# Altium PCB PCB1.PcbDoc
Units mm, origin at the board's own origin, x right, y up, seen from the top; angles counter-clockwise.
Board outline 150 x 100 mm, 8 copper layers (Top Layer, GND02, SIG03, SIG04, SIG05, SIG06, PWR07, Bottom Layer), stack 1.535 mm thick; 98 components, 234 nets, 1115 pads, 0 vias.
Unrouted connection lines stored in the file: 524.
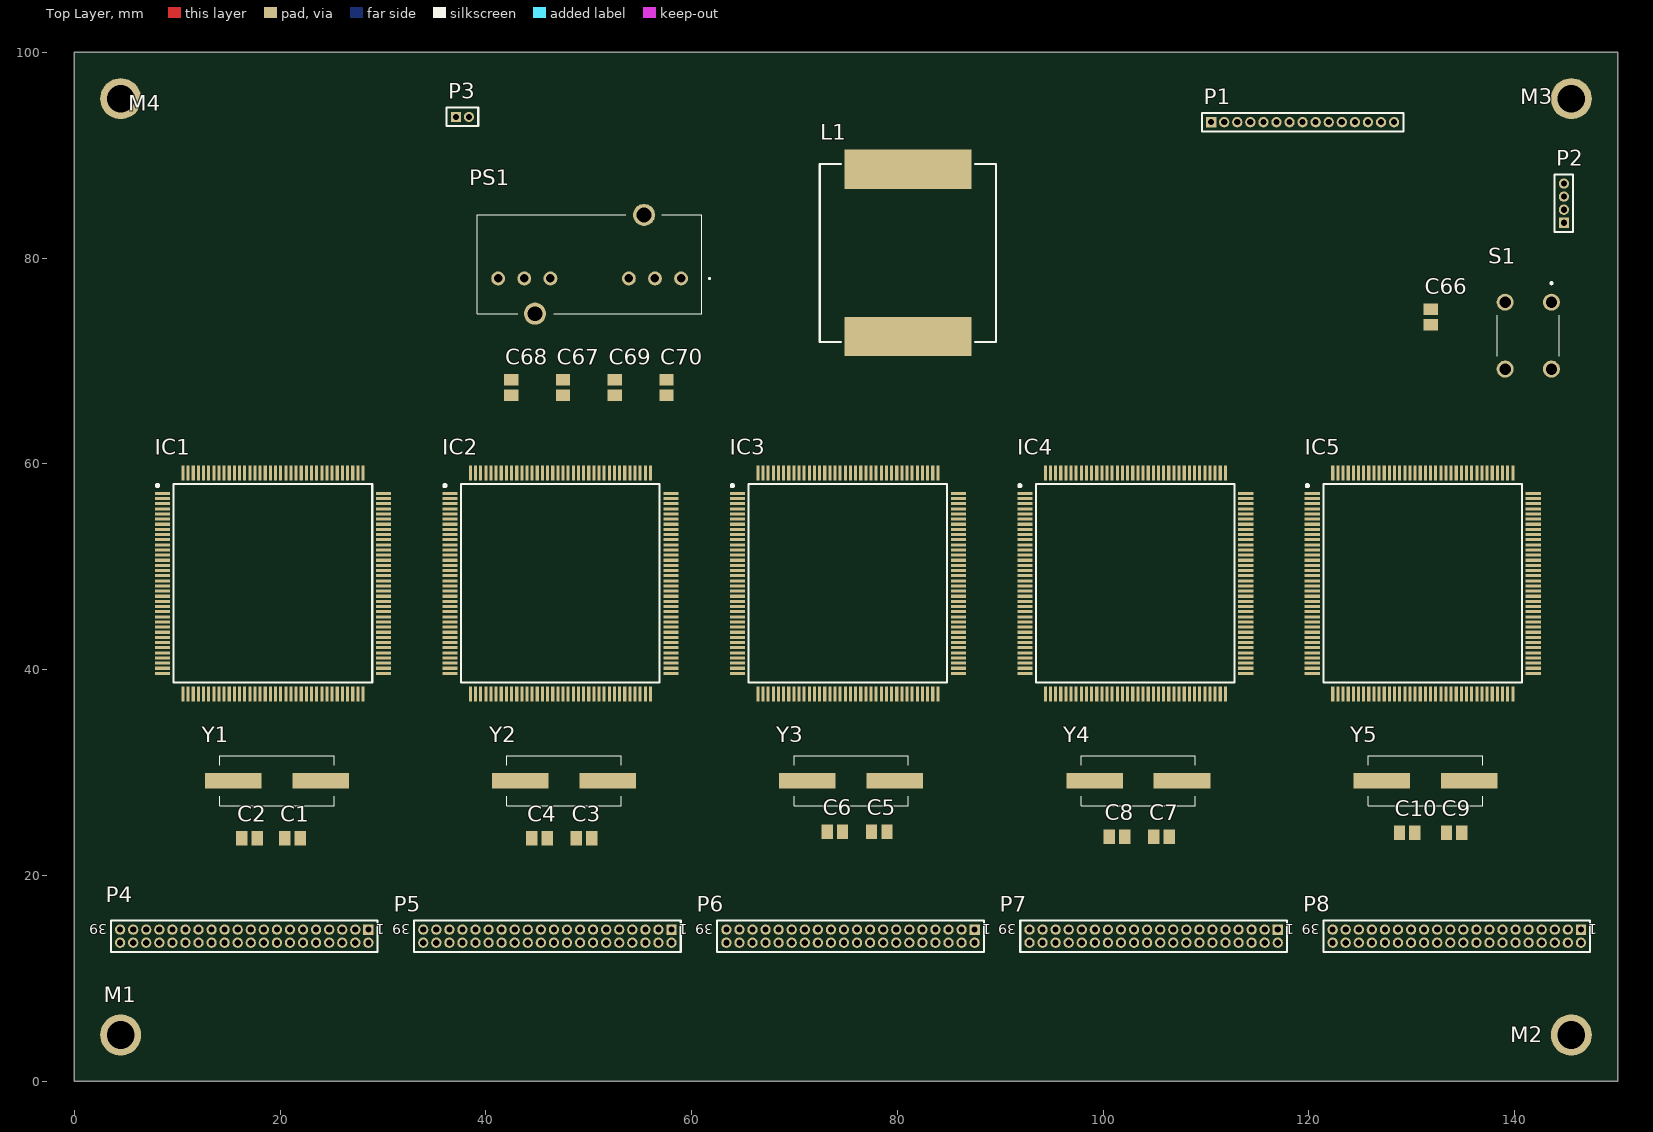
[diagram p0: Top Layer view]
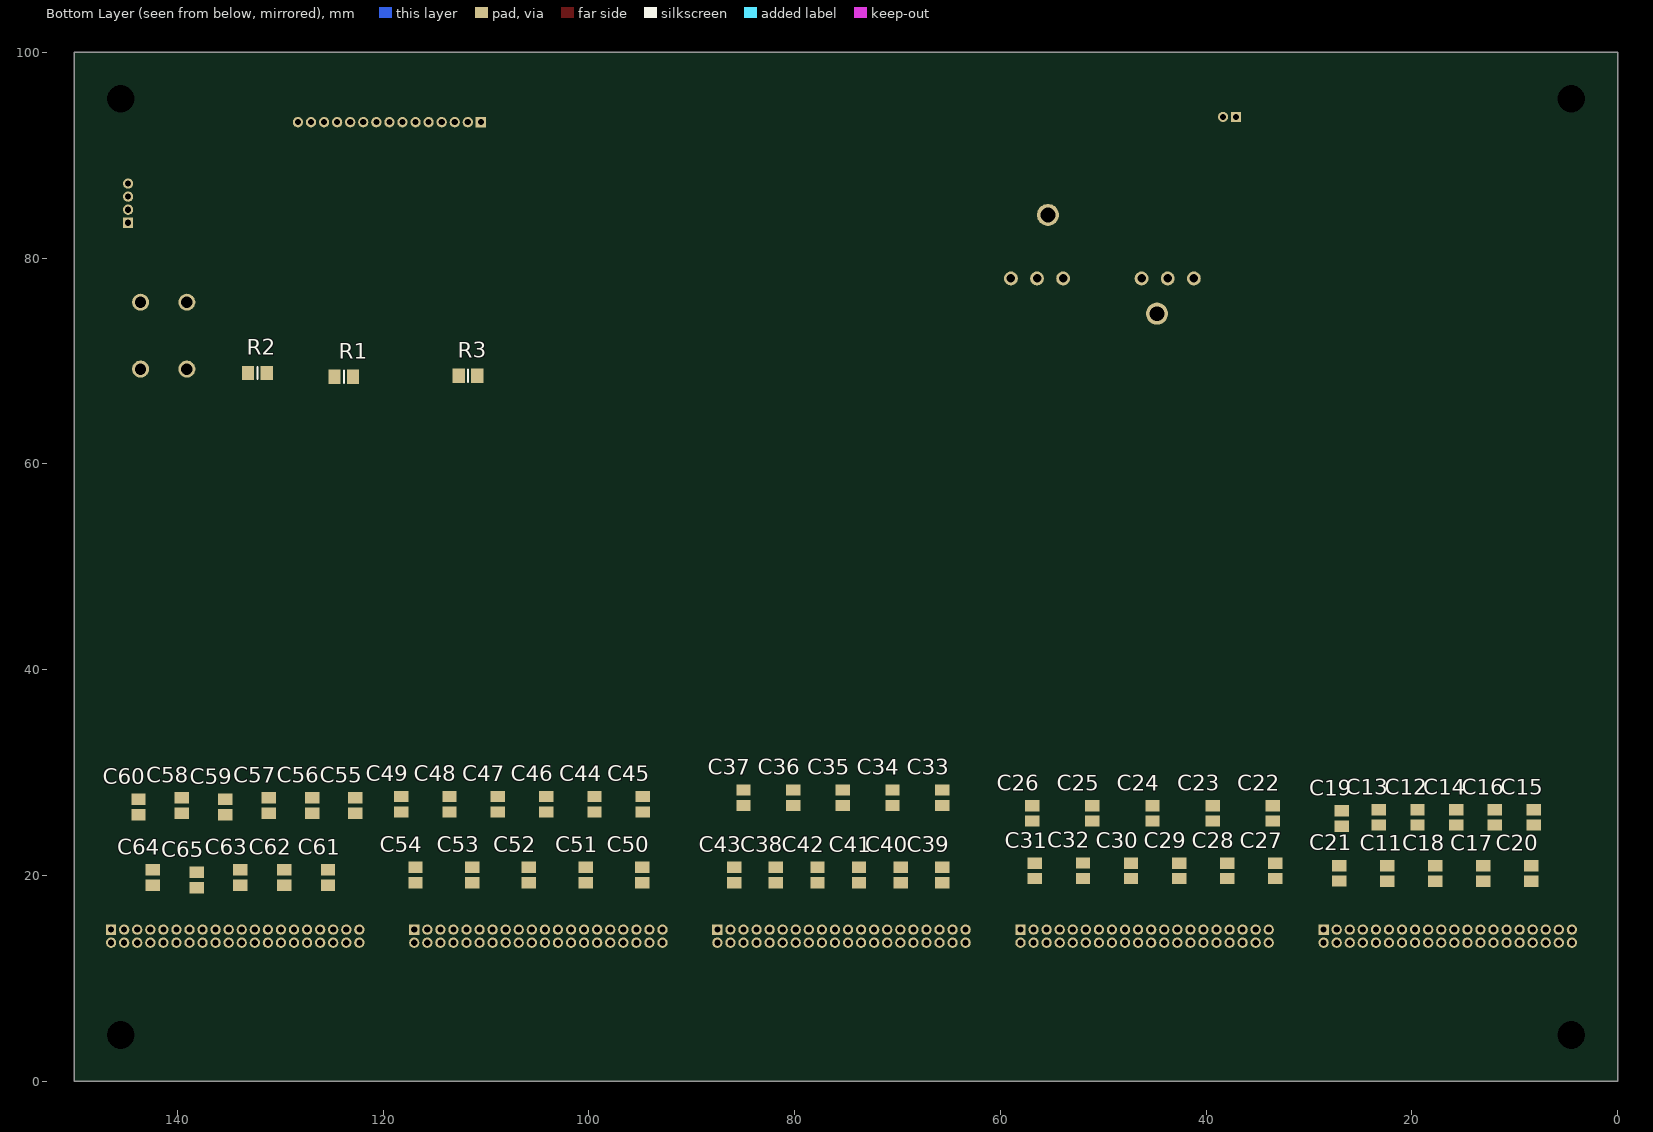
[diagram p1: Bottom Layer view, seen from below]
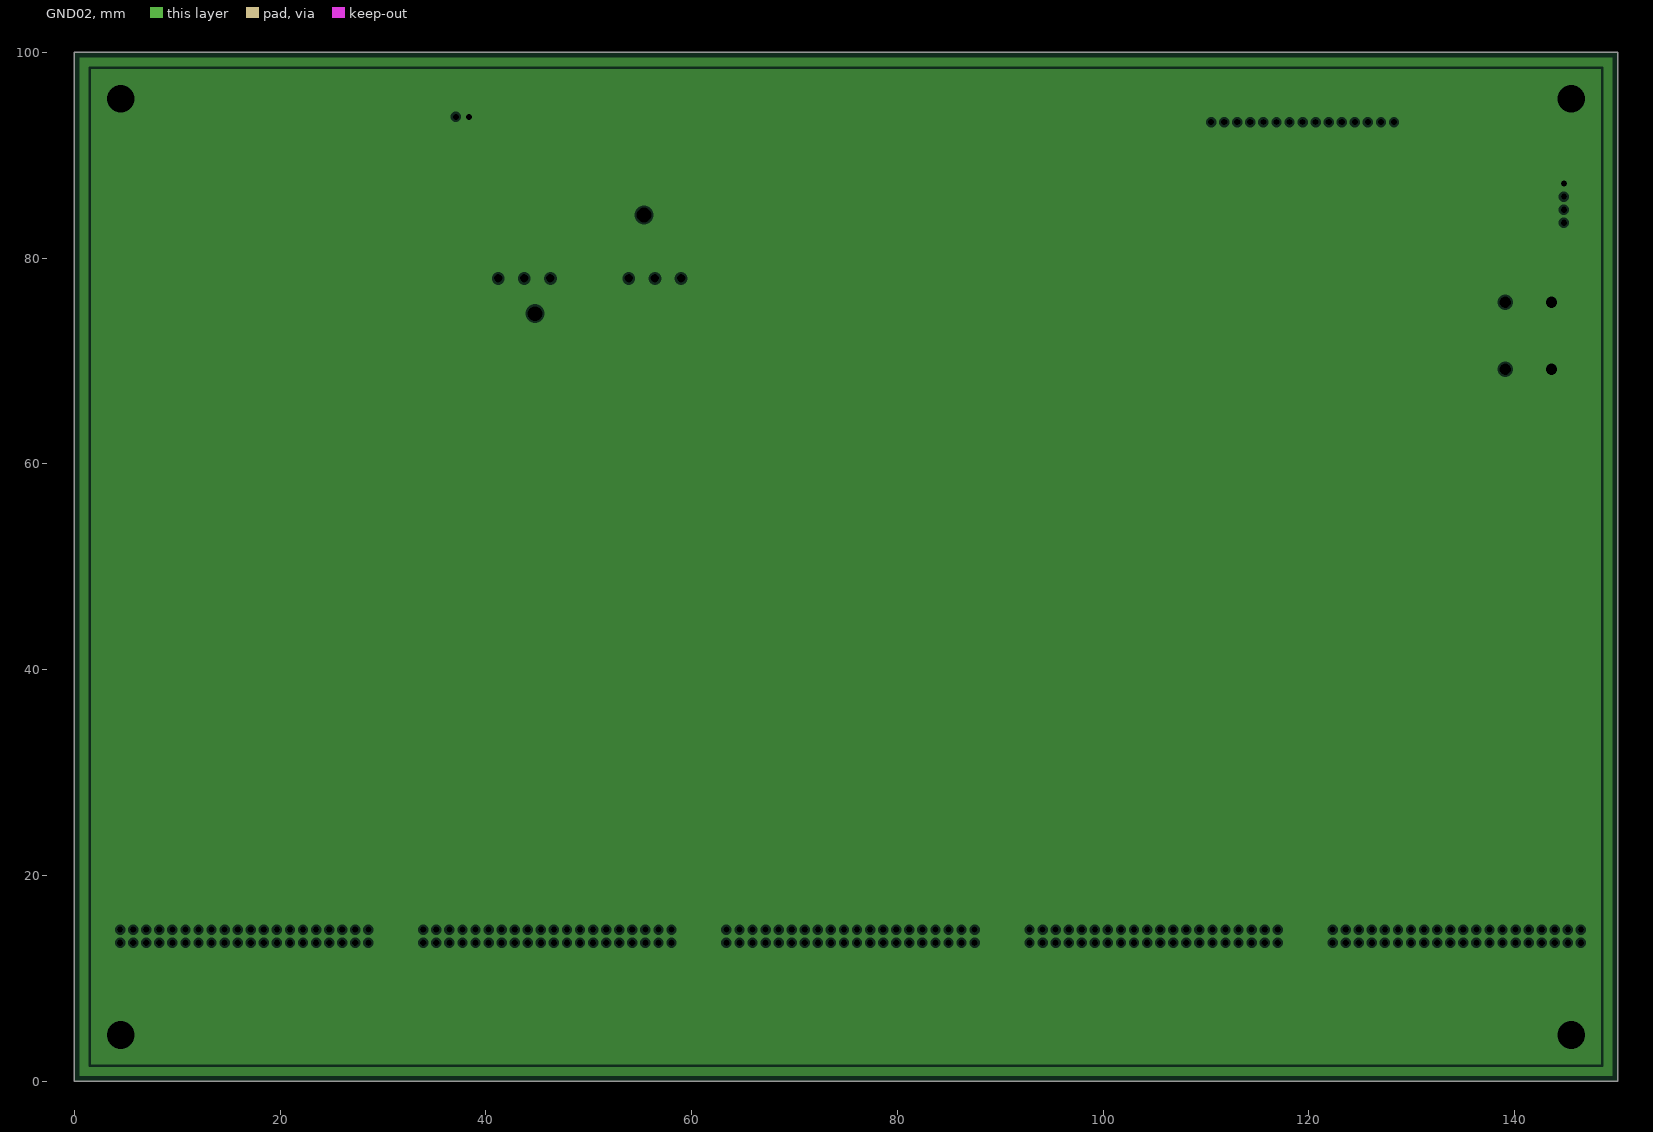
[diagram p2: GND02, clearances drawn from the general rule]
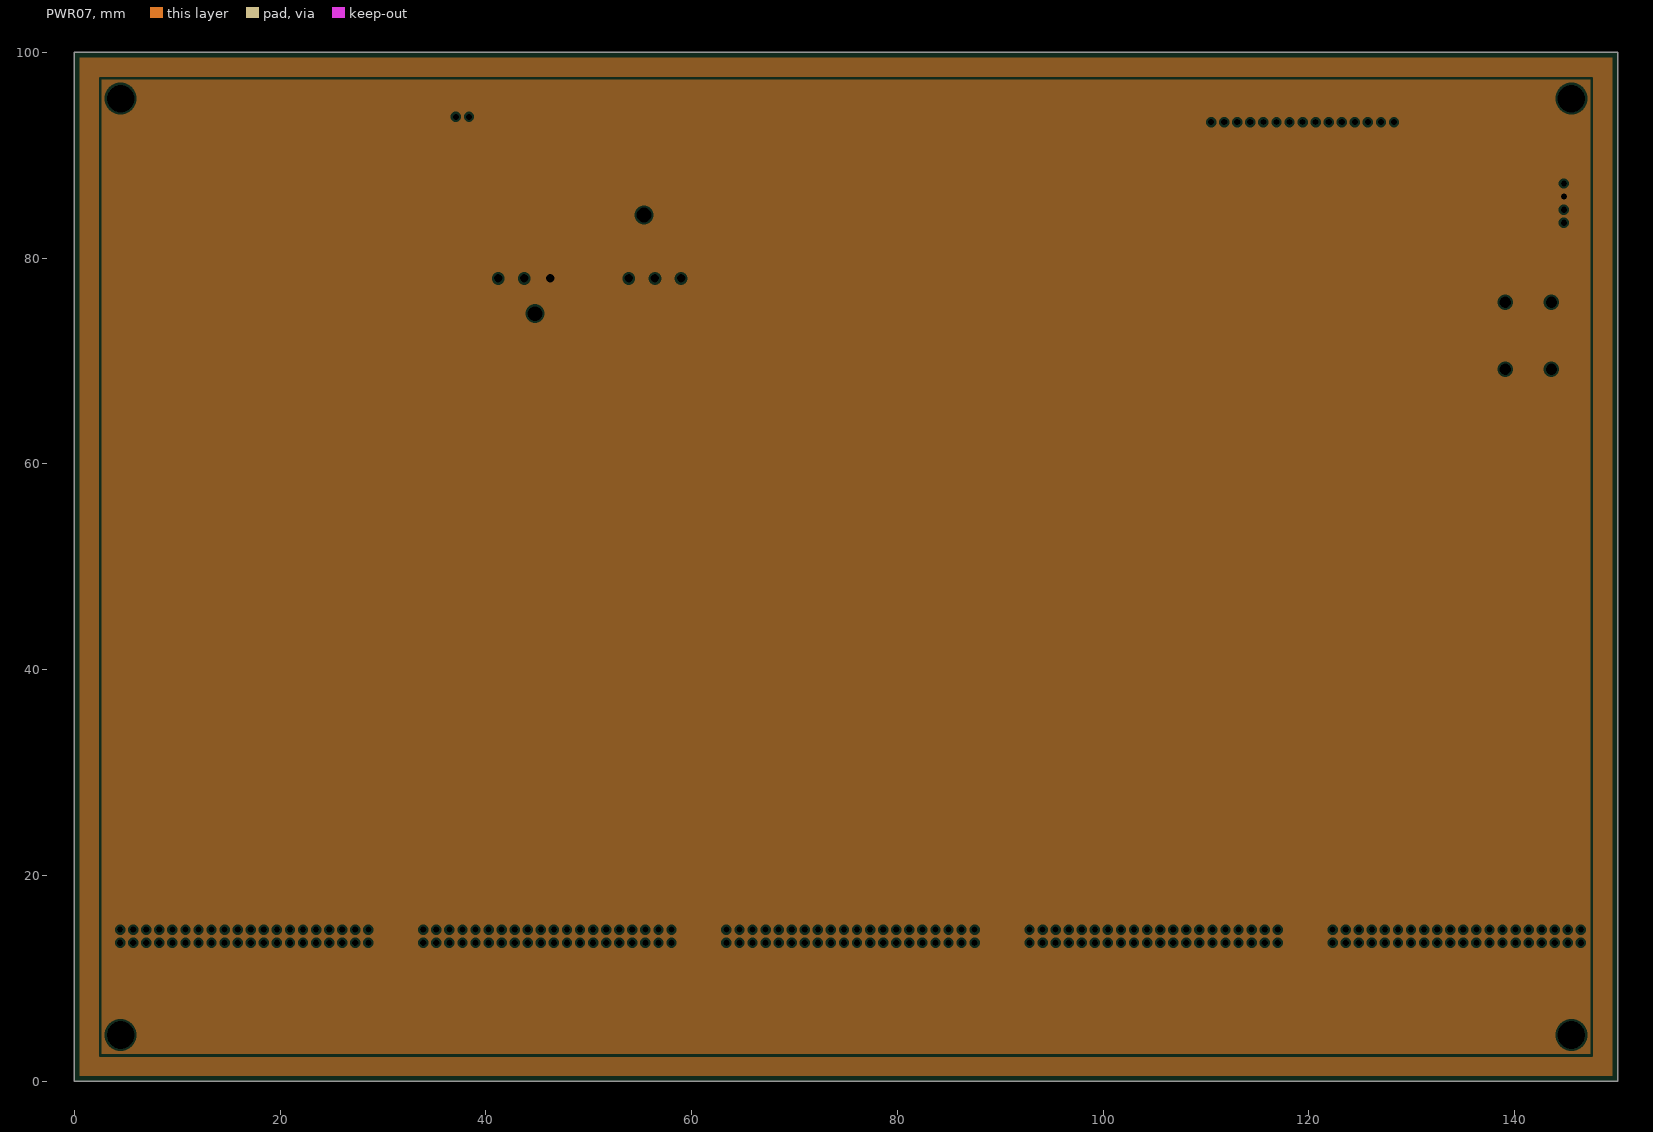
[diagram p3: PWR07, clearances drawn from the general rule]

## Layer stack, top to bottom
Top Solder: solder mask 0.0254, SM-001, Dk 4
Top Layer: signal copper 0.035
Dielectric 1: prepreg 0.0711, PP-006, Dk 4.1
Dielectric 2: prepreg 0.0711, PP-006, Dk 4.1
GND02: plane copper 0.035, net GND
Dielectric 3: core 0.2286, Core-027, Dk 4.5
SIG03: signal copper 0.035
Dielectric 4: prepreg 0.0711, PP-006, Dk 4.1
Dielectric 5: prepreg 0.0711, PP-006, Dk 4.1
SIG04: signal copper 0.035
Dielectric 6: core 0.2286, Core-027, Dk 4.5
SIG05: signal copper 0.035
Dielectric 7: prepreg 0.0711, PP-006, Dk 4.1
Dielectric 8: prepreg 0.0711, PP-006, Dk 4.1
SIG06: signal copper 0.035
Dielectric 9: core 0.2286, Core-027, Dk 4.5
PWR07: plane copper 0.035, net 3.3V
Dielectric 10: prepreg 0.0711, PP-006, Dk 4.1
Dielectric 11: prepreg 0.0711, PP-006, Dk 4.1
Bottom Layer: signal copper 0.035
Bottom Solder: solder mask 0.0254, SM-001, Dk 4

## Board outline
0,0 0,100 150,100 150,0

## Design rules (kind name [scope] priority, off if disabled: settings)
Clearance [istrack>(InDifferentialPairClass('All Differential Pairs')) vs (IsTrack)] p1: gap=0.305 ignorepadtopadclearanceinfootprint=TRUE except(0: Arc-Hole Track-Hole SMDPad-Hole THPad-Hole Via-Hole Fill-Hole Poly-Hole Region-Hole Text-Hole)
Clearance All [All] p2: gap=0.114 ignorepadtopadclearanceinfootprint=TRUE except(0: Arc-Hole Track-Hole SMDPad-Hole THPad-Hole Via-Hole Fill-Hole Poly-Hole Region-Hole Text-Hole)
Clearance Via_Poly [IsVia vs inpoly] p3: gap=0.127 ignorepadtopadclearanceinfootprint=TRUE except(0: Arc-Hole Track-Hole SMDPad-Hole THPad-Hole Via-Hole Fill-Hole Poly-Hole Region-Hole Text-Hole)
Clearance Poly [Isvia vs (InPolygon)] p4: gap=0.254 ignorepadtopadclearanceinfootprint=TRUE except(0: Arc-Hole Track-Hole SMDPad-Hole THPad-Hole Via-Hole Fill-Hole Poly-Hole Region-Hole Text-Hole)
PlaneClearance [All] p1: clearance=0.203
PlaneConnect [All] p1: planeconnectstyle=Relief reliefexpansion=0.152 reliefentries=4 reliefconductorwidth=0.254 reliefairgap=0.203
PolygonConnect [All] p1: connectstyle=Relief reliefconductorwidth=0.254 reliefentries=4 polygonreliefangle="90 Angle" airgapwidth=0.254
PolygonConnect PolygonConnect_Via [IsVia] p2: connectstyle=Direct reliefconductorwidth=0.254 reliefentries=4 polygonreliefangle="90 Angle" airgapwidth=0.254
RoutingVias [All] p1: holewidth=0.2 width=0.4 viastyle="Through Hole" minholewidth=0.2 minwidth=0.4 maxholewidth=0.2 maxwidth=0.4
SolderMaskExpansion [All] p1: expansion=0.102 istentingtop=FALSE
Width Diff_pair [(InDifferentialPairClass('100'))] p1: maxlimit=0.114 minlimit=0.114 preferedwidth=0.114
Width Width_1 [All] p2: maxlimit=1.524 minlimit=0.152 preferedwidth=0.152 minimp=50.000000 maximp=50.000000 favimp=50.000000
Width PWR [InNetClass('PWR')] p3: maxlimit=1.524 minlimit=0.254 preferedwidth=0.305
28 further rules are at their usual default settings.

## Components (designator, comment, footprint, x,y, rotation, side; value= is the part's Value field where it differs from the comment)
C1 "30pF" c0805 21.209,23.622 r180 top
C2 "30pF" c0805 17.018,23.622 r180 top
C3 "30pF" c0805 49.53,23.622 r180 top
C4 "30pF" c0805 45.212,23.622 r180 top
C5 "30pF" c0805 78.232,24.257 r180 top
C6 "30pF" c0805 73.914,24.257 r180 top
C7 "30pF" c0805 105.664,23.749 r180 top
C8 "30pF" c0805 101.346,23.749 r180 top
C9 "30pF" c0805 134.112,24.13 r180 top
C10 "30pF" c0805 129.54,24.13 r0 top
C11 "100nF" c0805 22.384,20.181 r270 bottom
C12 "100nF" c0805 19.454,25.649 r90 bottom
C13 "100nF" c0805 23.216,25.649 r90 bottom
C14 "100nF" c0805 15.692,25.649 r90 bottom
C15 "100nF" c0805 8.168,25.649 r90 bottom
C16 "100nF" c0805 11.93,25.649 r90 bottom
C17 "100nF" c0805 13.049,20.179 r90 bottom
C18 "100nF" c0805 17.716,20.179 r90 bottom
C19 "100nF" c0805 26.797,25.527 r90 bottom
C20 "100nF" c0805 8.382,20.193 r90 bottom
C21 "100nF" c0805 27.051,20.205 r270 bottom
C22 "100nF" c0805 33.528,26.035 r90 bottom
C23 "100nF" c0805 39.37,26.035 r90 bottom
C24 "100nF" c0805 45.212,26.035 r90 bottom
C25 "100nF" c0805 51.054,26.035 r90 bottom
C26 "100nF" c0805 56.896,26.035 r90 bottom
C27 "100nF" c0805 33.274,20.447 r90 bottom
C28 "100nF" c0805 37.948,20.447 r90 bottom
C29 "100nF" c0805 42.621,20.447 r90 bottom
C30 "100nF" c0805 47.295,20.447 r90 bottom
C31 "100nF" c0805 56.642,20.447 r90 bottom
C32 "100nF" c0805 51.968,20.459 r90 bottom
C33 "100nF" c0805 65.659,27.547 r90 bottom
C34 "100nF" c0805 70.485,27.547 r90 bottom
C35 "100nF" c0805 75.311,27.547 r90 bottom
C36 "100nF" c0805 80.137,27.547 r90 bottom
C37 "100nF" c0805 84.963,27.547 r90 bottom
C38 "100nF" c0805 81.813,20.054 r90 bottom
C39 "100nF" c0805 65.659,20.054 r90 bottom
C40 "100nF" c0805 69.698,20.054 r90 bottom
C41 "100nF" c0805 73.736,20.054 r90 bottom
C42 "100nF" c0805 77.775,20.054 r90 bottom
C43 "100nF" c0805 85.852,20.054 r90 bottom
C44 "100nF" c0805 99.441,26.924 r90 bottom
C45 "100nF" c0805 94.742,26.924 r90 bottom
C46 "100nF" c0805 104.14,26.924 r90 bottom
C47 "100nF" c0805 108.839,26.924 r90 bottom
C48 "100nF" c0805 113.538,26.924 r90 bottom
C49 "100nF" c0805 118.237,26.924 r90 bottom
C50 "100nF" c0805 94.793,20.054 r90 bottom
C51 "100nF" c0805 100.305,20.054 r90 bottom
C52 "100nF" c0805 105.816,20.054 r90 bottom
C53 "100nF" c0805 111.328,20.054 r90 bottom
C54 "100nF" c0805 116.84,20.054 r90 bottom
C55 "100nF" c0805 122.682,26.797 r90 bottom
C56 "100nF" c0805 126.898,26.797 r90 bottom
C57 "100nF" c0805 131.115,26.797 r90 bottom
C58 "100nF" c0805 139.548,26.797 r90 bottom
C59 "100nF" c0805 135.331,26.658 r90 bottom
C60 "100nF" c0805 143.764,26.658 r90 bottom
C61 "100nF" c0805 125.349,19.812 r270 bottom
C62 "100nF" c0805 129.603,19.812 r90 bottom
C63 "100nF" c0805 133.858,19.812 r90 bottom
C64 "100nF" c0805 142.367,19.812 r90 bottom
C65 "100nF" c0805 138.112,19.546 r90 bottom
C66 "100nF" c0805 131.826,74.283 r90 top
C67 "1nF" C0805 47.49,67.432 r90 top
C68 "1nF" C0805 42.458,67.432 r90 top value=10uF
C69 "1nF" C0805 52.522,67.432 r90 top
C70 "1nF" C0805 57.554,67.432 r90 top
IC1 "STM32F303ZET6" f303QFP50P2200X2200X160-144N 19.304,48.387 r0 top
IC2 "STM32F303ZET6" f303QFP50P2200X2200X160-144N 47.244,48.387 r0 top
IC3 "STM32F303ZET6" f303QFP50P2200X2200X160-144N 75.184,48.387 r0 top
IC4 "STM32F303ZET6" f303QFP50P2200X2200X160-144N 103.124,48.387 r0 top
IC5 "STM32F303ZET6" f303QFP50P2200X2200X160-144N 131.064,48.387 r0 top
L1 "IHLP6767GZER220M01" FP-IHLP-6767GZ-FP_3_825x1-MFG 81.026,80.507 r90 top
M1 "HOLE2R7-4" HOLE2R7-4#1 4.699,4.826 r0 top
M2 "HOLE2R7-4" HOLE2R7-4#2 144.78,5.461 r0 top
M3 "HOLE2R7-4" HOLE2R7-4#3 142.367,92.075 r0 top
M4 "HOLE2R7-4" HOLE2R7-4#4 7.112,91.44 r0 top
P1 "MHDR1X15" MHDR1X15 110.49,93.218 r0 top
P2 "MHDR1X4" MHDR1X4 144.78,83.439 r90 top
P3 "MHDR1X2" MHDR1X2 37.084,93.726 r0 top
P4 "MHDR2X20" MHDR2X20 28.575,14.732 r180 top
P5 "MHDR2X20" MHDR2X20 58.039,14.732 r180 top
P6 "MHDR2X20" MHDR2X20 87.503,14.732 r180 top
P7 "MHDR2X20" MHDR2X20 116.967,14.732 r180 top
P8 "MHDR2X20" MHDR2X20 146.431,14.732 r180 top
PS1 "TMR_6-2415WIR" TMR62410WIR 58.972,78.026 r180 top
R1 "10K" 6-0805_N 123.814,68.453 r180 bottom value=100K
R2 "10K" 6-0805_N 132.218,68.834 r180 bottom
R3 "10k" 6-0805_N 111.749,68.58 r180 bottom
S1 "B3F-1025" B3F1025 143.565,75.715 r90 top
Y1 "ATS08ASM-1E" ATS040SM1 19.685,29.21 r180 top
Y2 "ATS08ASM-1E" ATS040SM1 47.593,29.21 r180 top
Y3 "ATS08ASM-1E" ATS040SM1 75.501,29.21 r180 top
Y4 "ATS08ASM-1E" ATS040SM1 103.41,29.21 r180 top
Y5 "ATS08ASM-1E" ATS040SM1 131.318,29.21 r180 top

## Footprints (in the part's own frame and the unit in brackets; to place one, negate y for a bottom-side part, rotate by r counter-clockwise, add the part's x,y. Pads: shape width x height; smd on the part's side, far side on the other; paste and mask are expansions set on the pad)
6-0805_N [mm] "Chip Resistor, Body 2.0x1.2mm, IPC Medium Density"
  rect 1.2x1.4 smd: 1(-0.9,0) 2(0.9,0)
  silkscreen extent 0,-0.6 0,0.6, body extent -1.07,-0.7 1.07,0.7, height 0.7
ATS040SM1 [mm]
  rect 5.5x1.5 smd: 1(-4.25,0) 2(4.25,0)
  silkscreen extent -5.55,-2.41 5.55,2.41, body extent -6.85,-2.41 6.85,2.41, height 4.4
B3F1025 [mm]
  round 1.65 hole 1.1: 1(0,0) 2(-6.5,0) 3(0,4.5) 4(-6.5,4.5)
  silkscreen extent -5.25,-0.75 1.95,5.25, body extent -6.95,-0.75 0.45,5.25, height 5.3
c0805 [mm] "Chip Capacitor, Body 2.0x1.3mm, IPC High Density"
  rect 1.1x1.4 smd: 1(-0.75,0) 2(0.75,0)
  body extent -1.1,-0.72 1.1,0.72, height 1.4
C0805 [mm] "Chip Capacitor, Body 2.0x1.3mm, IPC High Density"
  rect 1.1x1.4 smd: 1(-0.75,0) 2(0.75,0)
  body extent -1.1,-0.72 1.1,0.72, height 1.4
f303QFP50P2200X2200X160-144N [mm]
  rect 1.475x0.3 smd: 1(-10.738,8.75) 2(-10.738,8.25) 3(-10.738,7.75) 4(-10.738,7.25) 5(-10.738,6.75) 6(-10.738,6.25) 7(-10.738,5.75) 8(-10.738,5.25) 9(-10.738,4.75) 10(-10.738,4.25) 11(-10.738,3.75) 12(-10.738,3.25) 13(-10.738,2.75) 14(-10.738,2.25) 15(-10.738,1.75) 16(-10.738,1.25) 17(-10.738,0.75) 18(-10.738,0.25) 19(-10.738,-0.25) 20(-10.738,-0.75) 21(-10.738,-1.25) 22(-10.738,-1.75) 23(-10.738,-2.25) 24(-10.738,-2.75) 25(-10.738,-3.25) 26(-10.738,-3.75) 27(-10.738,-4.25) 28(-10.738,-4.75) 29(-10.738,-5.25) 30(-10.738,-5.75) 31(-10.738,-6.25) 32(-10.738,-6.75) 33(-10.738,-7.25) 34(-10.738,-7.75) 35(-10.738,-8.25) 36(-10.738,-8.75) 73(10.738,-8.75) 74(10.738,-8.25) 75(10.738,-7.75) 76(10.738,-7.25) 77(10.738,-6.75) 78(10.738,-6.25) 79(10.738,-5.75) 80(10.738,-5.25) 81(10.738,-4.75) 82(10.738,-4.25) 83(10.738,-3.75) 84(10.738,-3.25) 85(10.738,-2.75) 86(10.738,-2.25) 87(10.738,-1.75) 88(10.738,-1.25) 89(10.738,-0.75) 90(10.738,-0.25) 91(10.738,0.25) 92(10.738,0.75) 93(10.738,1.25) 94(10.738,1.75) 95(10.738,2.25) 96(10.738,2.75) 97(10.738,3.25) 98(10.738,3.75) 99(10.738,4.25) 100(10.738,4.75) 101(10.738,5.25) 102(10.738,5.75) 103(10.738,6.25) 104(10.738,6.75) 105(10.738,7.25) 106(10.738,7.75) 107(10.738,8.25) 108(10.738,8.75)
  rect 0.3x1.475 smd: 37(-8.75,-10.738) 38(-8.25,-10.738) 39(-7.75,-10.738) 40(-7.25,-10.738) 41(-6.75,-10.738) 42(-6.25,-10.738) 43(-5.75,-10.738) 44(-5.25,-10.738) 45(-4.75,-10.738) 46(-4.25,-10.738) 47(-3.75,-10.738) 48(-3.25,-10.738) 49(-2.75,-10.738) 50(-2.25,-10.738) 51(-1.75,-10.738) 52(-1.25,-10.738) 53(-0.75,-10.738) 54(-0.25,-10.738) 55(0.25,-10.738) 56(0.75,-10.738) 57(1.25,-10.738) 58(1.75,-10.738) 59(2.25,-10.738) 60(2.75,-10.738) 61(3.25,-10.738) 62(3.75,-10.738) 63(4.25,-10.738) 64(4.75,-10.738) 65(5.25,-10.738) 66(5.75,-10.738) 67(6.25,-10.738) 68(6.75,-10.738) 69(7.25,-10.738) 70(7.75,-10.738) 71(8.25,-10.738) 72(8.75,-10.738) 109(8.75,10.738) 110(8.25,10.738) 111(7.75,10.738) 112(7.25,10.738) 113(6.75,10.738) 114(6.25,10.738) 115(5.75,10.738) 116(5.25,10.738) 117(4.75,10.738) 118(4.25,10.738) 119(3.75,10.738) 120(3.25,10.738) 121(2.75,10.738) 122(2.25,10.738) 123(1.75,10.738) 124(1.25,10.738) 125(0.75,10.738) 126(0.25,10.738) 127(-0.25,10.738) 128(-0.75,10.738) 129(-1.25,10.738) 130(-1.75,10.738) 131(-2.25,10.738) 132(-2.75,10.738) 133(-3.25,10.738) 134(-3.75,10.738) 135(-4.25,10.738) 136(-4.75,10.738) 137(-5.25,10.738) 138(-5.75,10.738) 139(-6.25,10.738) 140(-6.75,10.738) 141(-7.25,10.738) 142(-7.75,10.738) 143(-8.25,10.738) 144(-8.75,10.738)
  silkscreen extent -11.35,-9.65 9.65,9.65, body extent -11,-11 11,11, height 1.6
FP-IHLP-6767GZ-FP_3_825x1-MFG [mm]
  rect 3.825x12.32 smd paste+0 mask+0: 1(-8.117,0) 2(8.117,0)
  silkscreen extent -8.64,-8.57 8.64,8.57, body extent -10.13,-8.67 10.13,8.67, height 0.25
HOLE2R7-4#1 [mm] "HOLE2R7-4"
  round 4 / inner round 1.524 / far side round 1.524 hole 2.7: 1(-0.199,-0.326)
HOLE2R7-4#2 [mm] "HOLE2R7-4"
  round 4 / inner round 1.524 / far side round 1.524 hole 2.7: 1(0.72,-0.961)
HOLE2R7-4#3 [mm] "HOLE2R7-4"
  round 4 / inner round 1.524 / far side round 1.524 hole 2.7: 1(3.133,3.425)
HOLE2R7-4#4 [mm] "HOLE2R7-4"
  round 4 / inner round 1.524 / far side round 1.524 hole 2.7: 1(-2.612,4.06)
MHDR1X2 [mm] "Connector; Header; 2 Position"
  rect 1x1 hole 0.6: 1(0,0)
  round 1 hole 0.6: 2(1.27,0)
  silkscreen extent -0.9,-0.9 2.17,0.9
MHDR1X4 [mm] "Connector; Header; 4 Position"
  rect 1x1 hole 0.6: 1(0,0)
  round 1 hole 0.6: 2(1.27,0) 3(2.54,0) 4(3.81,0)
  silkscreen extent -0.9,-0.9 4.71,0.9
MHDR1X15 [mm] "Connector; Header; 15 Position"
  rect 1x1 hole 0.6: 1(0,0)
  round 1 hole 0.6: 2(1.27,0) 3(2.54,0) 4(3.81,0) 5(5.08,0) 6(6.35,0) 7(7.62,0) 8(8.89,0) 9(10.16,0) 10(11.43,0) 11(12.7,0) 12(13.97,0) 13(15.24,0) 14(16.51,0) 15(17.78,0)
  silkscreen extent -0.9,-0.9 18.68,0.9
MHDR2X20 [mm] "Connector; Header; 20x2 Position"
  rect 1x1 hole 0.6: 1(0,0)
  round 1 hole 0.6: 2(0,1.27) 3(1.27,0) 4(1.27,1.27) 5(2.54,0) 6(2.54,1.27) 7(3.81,0) 8(3.81,1.27) 9(5.08,0) 10(5.08,1.27) 11(6.35,0) 12(6.35,1.27) 13(7.62,0) 14(7.62,1.27) 15(8.89,0) 16(8.89,1.27) 17(10.16,0) 18(10.16,1.27) 19(11.43,0) 20(11.43,1.27) 21(12.7,0) 22(12.7,1.27) 23(13.97,0) 24(13.97,1.27) 25(15.24,0) 26(15.24,1.27) 27(16.51,0) 28(16.51,1.27) 29(17.78,0) 30(17.78,1.27) 31(19.05,0) 32(19.05,1.27) 33(20.32,0) 34(20.32,1.27) 35(21.59,0) 36(21.59,1.27) 37(22.86,0) 38(22.86,1.27) 39(24.13,0) 40(24.13,1.27)
  silkscreen extent -0.9,-0.9 25.03,2.17
TMR62410WIR [mm]
  round 1.349 hole 0.83: 1(0,0) 2(2.54,0) 3(5.08,0) 6(12.7,0) 7(15.24,0) 8(17.78,0)
  round 2.145 hole 1.43: 9(3.6,-6.175) 10(14.2,3.425)
  silkscreen extent -2.8,-6.17 19.8,3.42, body extent -2.12,-5.95 19.72,3.75, height 14.7

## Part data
C1 C2 C3 C4 C5 C6 C7 C8 C9 C10: library part CP1
C11 C12 C13 C14 C15 C16 C17 C18 C19 C20 C21 C22 C23 C24 C25 C26 C27 C28 C29 C30 C31 C32 C33 C34 C35 C36 C37 C38 C39 C40 C41 C42 C43 C44 C45 C46 C47 C48 C49 C50 C51 C52 C53 C54 C55 C56 C57 C58 C59 C60 C61 C62 C63 C64 C65: library part Cap_0805
C66 C67 C68 C69 C70: library part C
L1: library part CMP-02424-000149-1, "Commercial Inductors, High Saturation Series 22uH 11A 26.5mΩ 20%", Case/Package=6767, Current Rating=11A, DC Resistance (DCR)=26.5mR, Inductance=22uH, Inductance Tolerance=20%, Max DC Current=23A, Max Operating Temperature=125°C, Min Operating Temperature=-55°C, Package Quantity=200, Self Resonant Frequency=2MHz, Test Frequency=100kHz
P1: "Header, 15-Pin"
P2: "Header, 4-Pin"
P3: "Header, 2-Pin"
P4 P5 P6 P7 P8: "Header, 20-Pin, Dual row"
PS1: "Power Supply", Manufacturer_Name="Traco Power", Manufacturer_Part_Number="TMR 6-2415WIR", Mouser Part Number=495-TMR6-2415WIR
R1 R2 R3: library part R
S1: "Switch", Manufacturer_Name="Omron Electronics", Mouser Part Number=653-B3F-1025
Y1 Y2 Y3 Y4 Y5: "Crystal or Oscillator", Manufacturer_Name=CTS, Mouser Part Number=774-ATS08ASM-1E

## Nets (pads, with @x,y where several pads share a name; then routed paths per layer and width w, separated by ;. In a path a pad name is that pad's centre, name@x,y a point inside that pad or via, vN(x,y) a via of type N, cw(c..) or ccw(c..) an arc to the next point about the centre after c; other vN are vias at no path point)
1_AD1_IN1: IC1.34 P4.1
1_AD1_IN2: IC1.35 P4.3
1_AD1_IN3: IC1.36 P4.5
1_AD1_IN4: IC1.37 P4.7
1_AD1_IN5: IC1.14 P4.9
1_AD1_IN6: IC1.26 P4.11
1_AD1_IN7: IC1.27 P4.13
1_AD1_IN8: IC1.28 P4.15
1_AD1_IN9: IC1.29 P4.17
1_AD1_IN10: IC1.12 P4.19
1_AD1_IN14: IC1.70 P4.21
1_AD2_IN1: IC1.40 P4.23
1_AD2_IN2: IC1.41 P4.25
1_AD2_IN3: IC1.42 P4.27
1_AD2_IN4: IC1.43 P4.29
1_AD2_IN5: IC1.44 P4.31
1_AD2_IN11: IC1.45 P4.33
1_AD2_IN12: IC1.48 P4.35
1_AD3_IN1: IC1.47 P4.37
1_AD3_IN2: IC1.60 P4.39
1_AD3_IN3: IC1.66 P4.2
1_AD3_IN5: IC1.74 P4.4
1_AD3_IN6: IC1.59 P4.6
1_AD3_IN7: IC1.79 P4.8
1_AD3_IN8: IC1.80 P4.10
1_AD3_IN9: IC1.81 P4.12
1_AD3_IN10: IC1.82 P4.14
1_AD3_IN11: IC1.85 P4.16
1_AD3_IN12: IC1.46 P4.18
1_AD3_IN13: IC1.58 P4.20
1_AD3_IN14: IC1.63 P4.22
1_AD3_IN15: IC1.64 P4.24
1_AD3_IN16: IC1.65 P4.26
1_AD4_IN1: IC1.67 P4.28
1_AD4_IN2: IC1.68 P4.30
1_AD4_IN3: IC1.73 P4.32
1_AD4_IN4: IC1.75 P4.34
1_AD4_IN5: IC1.76 P4.36
1_AD4_IN12: IC1.77 P4.38
1_AD4_IN13: IC1.78 P4.40
1_BOOT0: IC1.138 IC2.138 IC3.138 IC4.138 IC5.138 R1.2
1_NRST: C66.1 IC1.25 IC2.25 IC3.25 IC4.25 IC5.25 R2.1 S1.3 S1.4
1_SPI_MISO: IC1.134 P1.2
1_SPI_MOSI: IC1.135 P1.3
1_SPI_SCK: IC1.133 P1.1
1_SWCLK: IC1.109 IC2.109 IC3.109 IC4.109 IC5.109 P2.1
1_SWDIO: IC1.105 IC2.105 IC3.105 IC4.105 IC5.105 P2.2 R3.2
2_AD1_IN1: IC2.34 P5.1
2_AD1_IN2: IC2.35 P5.3
2_AD1_IN3: IC2.36 P5.5
2_AD1_IN4: IC2.37 P5.7
2_AD1_IN5: IC2.14 P5.9
2_AD1_IN6: IC2.26 P5.11
2_AD1_IN7: IC2.27 P5.13
2_AD1_IN8: IC2.28 P5.15
2_AD1_IN9: IC2.29 P5.17
2_AD1_IN10: IC2.12 P5.19
2_AD1_IN14: IC2.70 P5.21
2_AD2_IN1: IC2.40 P5.23
2_AD2_IN2: IC2.41 P5.25
2_AD2_IN3: IC2.42 P5.27
2_AD2_IN4: IC2.43 P5.29
2_AD2_IN5: IC2.44 P5.31
2_AD2_IN11: IC2.45 P5.33
2_AD2_IN12: IC2.48 P5.35
2_AD3_IN1: IC2.47 P5.37
2_AD3_IN2: IC2.60 P5.39
2_AD3_IN3: IC2.66 P5.2
2_AD3_IN5: IC2.74 P5.4
2_AD3_IN6: IC2.59 P5.6
2_AD3_IN7: IC2.79 P5.8
2_AD3_IN8: IC2.80 P5.10
2_AD3_IN9: IC2.81 P5.12
2_AD3_IN10: IC2.82 P5.14
2_AD3_IN11: IC2.85 P5.16
2_AD3_IN12: IC2.46 P5.18
2_AD3_IN13: IC2.58 P5.20
2_AD3_IN14: IC2.63 P5.22
2_AD3_IN15: IC2.64 P5.24
2_AD3_IN16: IC2.65 P5.26
2_AD4_IN1: IC2.67 P5.28
2_AD4_IN2: IC2.68 P5.30
2_AD4_IN3: IC2.73 P5.32
2_AD4_IN4: IC2.75 P5.34
2_AD4_IN5: IC2.76 P5.36
2_AD4_IN12: IC2.77 P5.38
2_AD4_IN13: IC2.78 P5.40
2_SPI_MISO: IC2.134 P1.5
2_SPI_MOSI: IC2.135 P1.6
2_SPI_SCK: IC2.133 P1.4
3.3V: C11.1 C12.1 C13.1 C14.1 C15.1 C16.1 C17.1 C18.1 C19.1 C20.1 C21.1 C22.1 C23.1 C24.1 C25.1 C26.1 C27.1 C28.1 C29.1 C30.1 C31.1 C32.1 C33.1 C34.1 C35.1 C36.1 C37.1 C38.1 C39.1 C40.1 C41.1 C42.1 C43.1 C44.1 C45.1 C46.1 C47.1 C48.1 C49.1 C50.1 C51.1 C52.1 C53.1 C54.1 C55.1 C56.1 C57.1 C58.1 C59.1 C60.1 C61.1 C62.1 C63.1 C64.1 C65.1 C69.2 C70.2 IC1.17 IC1.32 IC1.33 IC1.39 IC1.52 IC1.62 IC1.72 IC1.84 IC1.95 IC1.108 IC1.121 IC1.131 IC1.144 IC2.17 IC2.32 IC2.33 IC2.39 IC2.52 IC2.62 IC2.72 IC2.84 IC2.95 IC2.108 IC2.121 IC2.131 IC2.144 IC3.17 IC3.32 IC3.33 IC3.39 IC3.52 IC3.62 IC3.72 IC3.84 IC3.95 IC3.108 IC3.121 IC3.131 IC3.144 IC4.17 IC4.32 IC4.33 IC4.39 IC4.52 IC4.62 IC4.72 IC4.84 IC4.95 IC4.108 IC4.121 IC4.131 IC4.144 IC5.17 IC5.32 IC5.33 IC5.39 IC5.52 IC5.62 IC5.72 IC5.84 IC5.95 IC5.108 IC5.121 IC5.131 IC5.144 P2.3 PS1.6 R2.2 R3.1
3_AD1_IN1: IC3.34 P6.1
3_AD1_IN2: IC3.35 P6.3
3_AD1_IN3: IC3.36 P6.5
3_AD1_IN4: IC3.37 P6.7
3_AD1_IN5: IC3.14 P6.9
3_AD1_IN6: IC3.26 P6.11
3_AD1_IN7: IC3.27 P6.13
3_AD1_IN8: IC3.28 P6.15
3_AD1_IN9: IC3.29 P6.17
3_AD1_IN10: IC3.12 P6.19
3_AD1_IN14: IC3.70 P6.21
3_AD2_IN1: IC3.40 P6.23
3_AD2_IN2: IC3.41 P6.25
3_AD2_IN3: IC3.42 P6.27
3_AD2_IN4: IC3.43 P6.29
3_AD2_IN5: IC3.44 P6.31
3_AD2_IN11: IC3.45 P6.33
3_AD2_IN12: IC3.48 P6.35
3_AD3_IN1: IC3.47 P6.37
3_AD3_IN2: IC3.60 P6.39
3_AD3_IN3: IC3.66 P6.2
3_AD3_IN5: IC3.74 P6.4
3_AD3_IN6: IC3.59 P6.6
3_AD3_IN7: IC3.79 P6.8
3_AD3_IN8: IC3.80 P6.10
3_AD3_IN9: IC3.81 P6.12
3_AD3_IN10: IC3.82 P6.14
3_AD3_IN11: IC3.85 P6.16
3_AD3_IN12: IC3.46 P6.18
3_AD3_IN13: IC3.58 P6.20
3_AD3_IN14: IC3.63 P6.22
3_AD3_IN15: IC3.64 P6.24
3_AD3_IN16: IC3.65 P6.26
3_AD4_IN1: IC3.67 P6.28
3_AD4_IN2: IC3.68 P6.30
3_AD4_IN3: IC3.73 P6.32
3_AD4_IN4: IC3.75 P6.34
3_AD4_IN5: IC3.76 P6.36
3_AD4_IN12: IC3.77 P6.38
3_AD4_IN13: IC3.78 P6.40
3_SPI_MISO: IC3.134 P1.8
3_SPI_MOSI: IC3.135 P1.9
3_SPI_SCK: IC3.133 P1.7
4_AD1_IN1: IC4.34 P7.1
4_AD1_IN2: IC4.35 P7.3
4_AD1_IN3: IC4.36 P7.5
4_AD1_IN4: IC4.37 P7.7
4_AD1_IN5: IC4.14 P7.9
4_AD1_IN6: IC4.26 P7.11
4_AD1_IN7: IC4.27 P7.13
4_AD1_IN8: IC4.28 P7.15
4_AD1_IN9: IC4.29 P7.17
4_AD1_IN10: IC4.12 P7.19
4_AD1_IN14: IC4.70 P7.21
4_AD2_IN1: IC4.40 P7.23
4_AD2_IN2: IC4.41 P7.25
4_AD2_IN3: IC4.42 P7.27
4_AD2_IN4: IC4.43 P7.29
4_AD2_IN5: IC4.44 P7.31
4_AD2_IN11: IC4.45 P7.33
4_AD2_IN12: IC4.48 P7.35
4_AD3_IN1: IC4.47 P7.37
4_AD3_IN2: IC4.60 P7.39
4_AD3_IN3: IC4.66 P7.2
4_AD3_IN5: IC4.74 P7.4
4_AD3_IN6: IC4.59 P7.6
4_AD3_IN7: IC4.79 P7.8
4_AD3_IN8: IC4.80 P7.10
4_AD3_IN9: IC4.81 P7.12
4_AD3_IN10: IC4.82 P7.14
4_AD3_IN11: IC4.85 P7.16
4_AD3_IN12: IC4.46 P7.18
4_AD3_IN13: IC4.58 P7.20
4_AD3_IN14: IC4.63 P7.22
4_AD3_IN15: IC4.64 P7.24
4_AD3_IN16: IC4.65 P7.26
4_AD4_IN1: IC4.67 P7.28
4_AD4_IN2: IC4.68 P7.30
4_AD4_IN3: IC4.73 P7.32
4_AD4_IN4: IC4.75 P7.34
4_AD4_IN5: IC4.76 P7.36
4_AD4_IN12: IC4.77 P7.38
4_AD4_IN13: IC4.78 P7.40
4_SPI_MISO: IC4.134 P1.11
4_SPI_MOSI: IC4.135 P1.12
4_SPI_SCK: IC4.133 P1.10
5_AD1_IN1: IC5.34 P8.1
5_AD1_IN2: IC5.35 P8.3
5_AD1_IN3: IC5.36 P8.5
5_AD1_IN4: IC5.37 P8.7
5_AD1_IN5: IC5.14 P8.9
5_AD1_IN6: IC5.26 P8.11
5_AD1_IN7: IC5.27 P8.13
5_AD1_IN8: IC5.28 P8.15
5_AD1_IN9: IC5.29 P8.17
5_AD1_IN10: IC5.12 P8.19
5_AD1_IN14: IC5.70 P8.21
5_AD2_IN1: IC5.40 P8.23
5_AD2_IN2: IC5.41 P8.25
5_AD2_IN3: IC5.42 P8.27
5_AD2_IN4: IC5.43 P8.29
5_AD2_IN5: IC5.44 P8.31
5_AD2_IN11: IC5.45 P8.33
5_AD2_IN12: IC5.48 P8.35
5_AD3_IN1: IC5.47 P8.37
5_AD3_IN2: IC5.60 P8.39
5_AD3_IN3: IC5.66 P8.2
5_AD3_IN5: IC5.74 P8.4
5_AD3_IN6: IC5.59 P8.6
5_AD3_IN7: IC5.79 P8.8
5_AD3_IN8: IC5.80 P8.10
5_AD3_IN9: IC5.81 P8.12
5_AD3_IN10: IC5.82 P8.14
5_AD3_IN11: IC5.85 P8.16
5_AD3_IN12: IC5.46 P8.18
5_AD3_IN13: IC5.58 P8.20
5_AD3_IN14: IC5.63 P8.22
5_AD3_IN15: IC5.64 P8.24
5_AD3_IN16: IC5.65 P8.26
5_AD4_IN1: IC5.67 P8.28
5_AD4_IN2: IC5.68 P8.30
5_AD4_IN3: IC5.73 P8.32
5_AD4_IN4: IC5.75 P8.34
5_AD4_IN5: IC5.76 P8.36
5_AD4_IN12: IC5.77 P8.38
5_AD4_IN13: IC5.78 P8.40
5_SPI_MISO: IC5.134 P1.14
5_SPI_MOSI: IC5.135 P1.15
5_SPI_SCK: IC5.133 P1.13
GND: C1.2 C2.2 C3.2 C4.2 C5.2 C6.2 C7.2 C8.2 C9.2 C10.2 C11.2 C12.2 C13.2 C14.2 C15.2 C16.2 C17.2 C18.2 C19.2 C20.2 C21.2 C22.2 C23.2 C24.2 C25.2 C26.2 C27.2 C28.2 C29.2 C30.2 C31.2 C32.2 C33.2 C34.2 C35.2 C36.2 C37.2 C38.2 C39.2 C40.2 C41.2 C42.2 C43.2 C44.2 C45.2 C46.2 C47.2 C48.2 C49.2 C50.2 C51.2 C52.2 C53.2 C54.2 C55.2 C56.2 C57.2 C58.2 C59.2 C60.2 C61.2 C62.2 C63.2 C64.2 C65.2 C66.2 IC1.16 IC1.30 IC1.31 IC1.38 IC1.51 IC1.61 IC1.71 IC1.83 IC1.94 IC1.107 IC1.120 IC1.130 IC1.143 IC2.16 IC2.30 IC2.31 IC2.38 IC2.51 IC2.61 IC2.71 IC2.83 IC2.94 IC2.107 IC2.120 IC2.130 IC2.143 IC3.16 IC3.30 IC3.31 IC3.38 IC3.51 IC3.61 IC3.71 IC3.83 IC3.94 IC3.107 IC3.120 IC3.130 IC3.143 IC4.16 IC4.30 IC4.31 IC4.38 IC4.51 IC4.61 IC4.71 IC4.83 IC4.94 IC4.107 IC4.120 IC4.130 IC4.143 IC5.16 IC5.30 IC5.31 IC5.38 IC5.51 IC5.61 IC5.71 IC5.83 IC5.94 IC5.107 IC5.120 IC5.130 IC5.143 L1.1 M1.1 M2.1 M3.1 M4.1 P2.4 P3.2 R1.1 S1.1 S1.2
NetC1_1: C1.1 IC1.23 Y1.1
NetC2_1: C2.1 IC1.24 Y1.2
NetC3_1: C3.1 IC2.23 Y2.1
NetC4_1: C4.1 IC2.24 Y2.2
NetC5_1: C5.1 IC3.23 Y3.1
NetC6_1: C6.1 IC3.24 Y3.2
NetC7_1: C7.1 IC4.23 Y4.1
NetC8_1: C8.1 IC4.24 Y4.2
NetC9_1: C9.1 IC5.23 Y5.1
NetC10_1: C10.1 IC5.24 Y5.2
NetC67_1: C67.1 C68.1 C69.1 L1.2 PS1.1
NetC67_2: C67.2 PS1.7
NetC68_2: C68.2 C70.1 P3.1 PS1.2
pads on no net: IC1.1 IC1.2 IC1.3 IC1.4 IC1.5 IC1.6 IC1.7 IC1.8 IC1.9 IC1.10 IC1.11 IC1.13 IC1.15 IC1.18 IC1.19 IC1.20 IC1.21 IC1.22 IC1.49 IC1.50 IC1.53 IC1.54 IC1.55 IC1.56 IC1.57 IC1.69 IC1.86 IC1.87 IC1.88 IC1.89 IC1.90 IC1.91 IC1.92 IC1.93 IC1.96 IC1.97 IC1.98 IC1.99 IC1.100 IC1.101 IC1.102 IC1.103 IC1.104 IC1.106 IC1.110 IC1.111 IC1.112 IC1.113 IC1.114 IC1.115 IC1.116 IC1.117 IC1.118 IC1.119 IC1.122 IC1.123 IC1.124 IC1.125 IC1.126 IC1.127 IC1.128 IC1.129 IC1.132 IC1.136 IC1.137 IC1.139 IC1.140 IC1.141 IC1.142 IC2.1 IC2.2 IC2.3 IC2.4 IC2.5 IC2.6 IC2.7 IC2.8 IC2.9 IC2.10 IC2.11 IC2.13 IC2.15 IC2.18 IC2.19 IC2.20 IC2.21 IC2.22 IC2.49 IC2.50 IC2.53 IC2.54 IC2.55 IC2.56 IC2.57 IC2.69 IC2.86 IC2.87 IC2.88 IC2.89 IC2.90 IC2.91 IC2.92 IC2.93 IC2.96 IC2.97 IC2.98 IC2.99 IC2.100 IC2.101 IC2.102 IC2.103 IC2.104 IC2.106 IC2.110 IC2.111 IC2.112 IC2.113 IC2.114 IC2.115 IC2.116 IC2.117 IC2.118 IC2.119 IC2.122 IC2.123 IC2.124 IC2.125 IC2.126 IC2.127 IC2.128 IC2.129 IC2.132 IC2.136 IC2.137 IC2.139 IC2.140 IC2.141 IC2.142 IC3.1 IC3.2 IC3.3 IC3.4 IC3.5 IC3.6 IC3.7 IC3.8 IC3.9 IC3.10 IC3.11 IC3.13 IC3.15 IC3.18 IC3.19 IC3.20 IC3.21 IC3.22 IC3.49 IC3.50 IC3.53 IC3.54 IC3.55 IC3.56 IC3.57 IC3.69 IC3.86 IC3.87 IC3.88 IC3.89 IC3.90 IC3.91 IC3.92 IC3.93 IC3.96 IC3.97 IC3.98 IC3.99 IC3.100 IC3.101 IC3.102 IC3.103 IC3.104 IC3.106 IC3.110 IC3.111 IC3.112 IC3.113 IC3.114 IC3.115 IC3.116 IC3.117 IC3.118 IC3.119 IC3.122 IC3.123 IC3.124 IC3.125 IC3.126 IC3.127 IC3.128 IC3.129 IC3.132 IC3.136 IC3.137 IC3.139 IC3.140 IC3.141 IC3.142 IC4.1 IC4.2 IC4.3 IC4.4 IC4.5 IC4.6 IC4.7 IC4.8 IC4.9 IC4.10 IC4.11 IC4.13 IC4.15 IC4.18 IC4.19 IC4.20 IC4.21 IC4.22 IC4.49 IC4.50 IC4.53 IC4.54 IC4.55 IC4.56 IC4.57 IC4.69 IC4.86 IC4.87 IC4.88 IC4.89 IC4.90 IC4.91 IC4.92 IC4.93 IC4.96 IC4.97 IC4.98 IC4.99 IC4.100 IC4.101 IC4.102 IC4.103 IC4.104 IC4.106 IC4.110 IC4.111 IC4.112 IC4.113 IC4.114 IC4.115 IC4.116 IC4.117 IC4.118 IC4.119 IC4.122 IC4.123 IC4.124 IC4.125 IC4.126 IC4.127 IC4.128 IC4.129 IC4.132 IC4.136 IC4.137 IC4.139 IC4.140 IC4.141 IC4.142 IC5.1 IC5.2 IC5.3 IC5.4 IC5.5 IC5.6 IC5.7 IC5.8 IC5.9 IC5.10 IC5.11 IC5.13 IC5.15 IC5.18 IC5.19 IC5.20 IC5.21 IC5.22 IC5.49 IC5.50 IC5.53 IC5.54 IC5.55 IC5.56 IC5.57 IC5.69 IC5.86 IC5.87 IC5.88 IC5.89 IC5.90 IC5.91 IC5.92 IC5.93 IC5.96 IC5.97 IC5.98 IC5.99 IC5.100 IC5.101 IC5.102 IC5.103 IC5.104 IC5.106 IC5.110 IC5.111 IC5.112 IC5.113 IC5.114 IC5.115 IC5.116 IC5.117 IC5.118 IC5.119 IC5.122 IC5.123 IC5.124 IC5.125 IC5.126 IC5.127 IC5.128 IC5.129 IC5.132 IC5.136 IC5.137 IC5.139 IC5.140 IC5.141 IC5.142 PS1.3 PS1.8 PS1.9 PS1.10

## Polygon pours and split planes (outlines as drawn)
GND on GND02 (split plane): 148.371,1.629 1.629,1.629 1.629,98.371 148.371,98.371
no net on GND02 (split plane): 149.49,0.51 0.51,0.51 0.51,99.49 149.49,99.49
3.3V on PWR07 (split plane): 147.371,2.629 2.629,2.629 2.629,97.371 147.371,97.371
no net on PWR07 (split plane): 149.49,0.51 0.51,0.51 0.51,99.49 149.49,99.49

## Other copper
GND02 (plane layer: these items are gaps in the copper):
  lines w0.254: 1.5,1.5 148.5,1.5 148.5,98.5 1.5,98.5 1.5,1.5
PWR07 (plane layer: these items are gaps in the copper):
  lines w0.254: 2.5,2.5 2.5,97.5 147.5,97.5 147.5,2.5 2.5,2.5

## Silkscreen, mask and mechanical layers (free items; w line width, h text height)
Mechanical 1:
  lines w0.254: -6.147,1.484 -5.639,-0.04 ; -6.147,98.436 -5.639,99.96 ; -5.893,-0.04 -5.385,-0.04 ; -5.893,99.96 -5.385,99.96 ; -5.639,44.221 -5.639,-0.04 ; -5.639,55.699 -5.639,99.96 ; -5.131,1.484 -5.639,-0.04 ; -5.131,98.436 -5.639,99.96 ; -0.221,-3.429 -0.221,-2.921 ; 1.303,-3.683 -0.221,-3.175 ; 1.303,-2.667 -0.221,-3.175 ; 69.041,-3.175 -0.221,-3.175 ; 80.518,-3.175 149.779,-3.175 ; 148.255,-3.683 149.779,-3.175 ; 148.255,-2.667 149.779,-3.175 ; 149.779,-3.429 149.779,-2.921 ; 0,0 150,0 150,100 0,100 0,0
  text "100 (mm)" at -4.724,44.475 h1.52 r90
  text "150 (mm)" at 69.295,-4.089 h1.52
